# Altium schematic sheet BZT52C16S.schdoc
size 127 x 101 mm
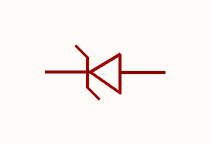
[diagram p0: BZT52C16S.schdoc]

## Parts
ZD?  bzt52c16s_c22617  [SOD-323_L1.8-W1.3-LS2.5-RD]  (value not drawn)

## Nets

Not connected (* = marked no-connect by the designer): ZD? 1(K) 2(A)

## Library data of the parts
ZD? = bzt52c16s_c22617: 二极管配置:1个独立式;稳压值(标称值):16V;稳压值(范围):15.3V~17.1V;耗散功率(Pd):200mW;; Manufacturer: CJ(江苏长电/长晶); AddInBom: yes; ModelId: db63db13d9e342eb939127d413d6200b; ModelTransform: 104.3305,51.181,0,0,0,0,0,-0.004,0; Diode Configuration: 1个独立式; Zener Voltage(Nom): 16V; Reverse Leakage Current (Ir): 100nA; Pd - Power Dissipation: 200mW; Impedance(Zzt): 40Ω; Impedance(Zzk): 200Ω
